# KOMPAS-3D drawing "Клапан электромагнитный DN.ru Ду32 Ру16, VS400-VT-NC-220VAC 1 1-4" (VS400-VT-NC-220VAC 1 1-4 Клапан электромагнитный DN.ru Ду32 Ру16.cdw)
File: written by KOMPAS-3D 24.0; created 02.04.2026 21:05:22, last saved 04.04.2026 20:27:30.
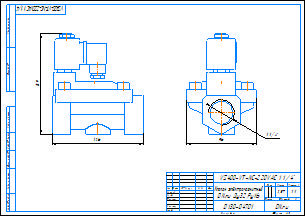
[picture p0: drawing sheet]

Document properties: c3d_UniqueCompID: ef56311e-7521-43dc-8291-0e6108b3d81d; Обозначение: VS400-ET-NC-220VAC 1; Наименование: Клапан электромагнитный DN.ru Ду25 Ру16; Автор: artio; Класс точности: c; Знак неуказанной шероховатости: Шероховатость не задана; Рассекать на разрезах: Да; c3d_UniqueCompID: ef56311e-7521-43dc-8291-0e6108b3d81d; Обозначение: VS400-ET-NC-220VAC 1-2; Наименование: Клапан электромагнитный DN.ru Ду15 Ру16; Автор: artio; Класс точности: c; Знак неуказанной шероховатости: Шероховатость не задана; Рассекать на разрезах: Да; c3d_UniqueCompID: ef56311e-7521-43dc-8291-0e6108b3d81d; Обозначение: VS400-ET-NC-220VAC 3-4; Наименование: Клапан электромагнитный DN.ru Ду20 Ру16; Автор: artio; Класс точности: c; Знак неуказанной шероховатости: Шероховатость не задана; Рассекать на разрезах: Да; c3d_UniqueCompID: ef56311e-7521-43dc-8291-0e6108b3d81d; Обозначение: VS400-ET-NC-220VAC 1 1-4; Наименование: Клапан электромагнитный DN.ru Ду32 Ру16; Автор: artio; Класс точности: c; Знак неуказанной шероховатости: Шероховатость не задана; Рассекать на разрезах: Да; c3d_UniqueCompID: ef56311e-7521-43dc-8291-0e6108b3d81d; Обозначение: VS400-ET-NC-220VAC 3-8; Наименование: Клапан электромагнитный DN.ru Ду10 Ру16; Автор: artio; Класс точности: c; Знак неуказанной шероховатости: Шероховатость не задана; Рассекать на разрезах: Да; Автор: artio; Форматы листов документа: A3; Полное имя файла: VS400-VT-NC-220VAC 1 1-4 Клапан электромагнитный DN.ru Ду32 Ру16.m3d; Масса: 2.569; Наименование: Клапан электромагнитный DN.ru Ду32 Ру16; Количество листов документа: 1; Примечание: D130-04701

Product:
- Body: Тело 1  | qty 1
    Масса: 4.144257
- Part/product: Клапан электромагнитный DN.ru Ду32 Ру16  | designation VS400-VT-NC-220VAC 1 1-4
    Масса: 2.569
    Раздел спецификации: Прочие изделия
    Примечание: D130-04701
    additional columns: ef56311e-7521-43dc-8291-0e6108b3d81d; VS400-ET-NC-220VAC 1 1-4; artio; c; Шероховатость не задана; Да

Views: Вид 1, Спереди
Referenced files in C:\Users\artio\OneDrive\Рабочий стол\Клапан электромагнитный DN.ru VS4x-xT-NC-x\DN10\: VS400-ET-NC-220VAC 3-8 Клапан электромагнитный DN.ru Ду10 Ру16.m3d, VS400-ET-NC-220VAC 3-8 Клапан электромагнитный DN.ru Ду10 Ру16.cdw
Referenced files in C:\Users\artio\OneDrive\Рабочий стол\Клапан электромагнитный DN.ru\VS400-VT-NC\VS400-VT-NC-220VAC\: VS400-VT-NC-220VAC 1 1-4 Клапан электромагнитный DN.ru Ду32 Ру16.m3d
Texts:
  VS400-VT-NC-220VAC 1 1-4
  Клапан электромагнитный
  DN.ru Ду32 Ру16
  VS400-VT-NC-220VAC 1 1/4"
  VS400-VT-NC-220VAC 1 1/4"-
  Клапан электромагнитный DN.ru Ду32 Ру16
  VS400-VT-NC-220VAC 1 1-4 Клапан электромагнитный DN.ru Ду32 Ру16
Dimensions and other numbers on the sheet: 0; 3; 2; 4; 96; 1 1/4"; 1:1; 1; 2,57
